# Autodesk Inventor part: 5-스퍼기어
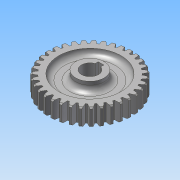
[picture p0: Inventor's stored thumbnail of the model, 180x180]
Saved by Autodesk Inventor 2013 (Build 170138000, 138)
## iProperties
Created: 2013-08
Part Number: 5-스퍼기어
Material: 강
Document SubType Name: Modeling
Designer: 한국산업디자인학원
Categories: <?xml version="1.0" encoding="UTF-16"?> <MemberInstance><Categories><FamilyTemplate><FamilyTemplateParameter ValueType="xs:double" Id="1" ObjectReferenceKey="da
Density: 1 g/cm^3
CustomPartVersion: 1
Author: 한국산업디자인학원
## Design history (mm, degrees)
sketch "Sketch1"
  geometry: C1 r 37 at (0, 0)
  constraints: 1 centre point
  dimensions: "d0" = 74 diameter of C1 (= da_da)
extrude "Extrusion1" new body sketch "Sketch1" distance "d1" = 15 (= da_b); taper "d2" = 0 deg
chamfer "모따기1" distance "d49" = 1; stored, may be unused: second distance "d50" = 2, angle "d51" = 45 deg
workplane "Work Plane2"
feature "피치 지름" dims "d4" = 10, "d5" = 0
workplane "Work Plane8"
workplane "Work Plane9"
feature "스퍼 기어" dims "da_b" = 15, "da_d" = 70, "da_aw" = 70, "da_da" = 74, "da_df" = 65, "da_dw" = 70, angle "da_beta" = 0 deg, "da_lefttooth" = 0, "da_righttooth" = 0
sketch "스케치3"
  geometry: C1 r 12.5 at (0, 0); C2 r 27.5 at (0, 0); A1 r 36 centre (0, 0) between (-30.704, -18.795) and (-29.35, -20.846) reference; A2 r 36 centre (0, 0) between (-5.215, 35.62) and (-7.633, 35.181) reference
  constraints: 2 centre point, 2 coincident
  dimensions: "d52" = 25 diameter of C1; "d54" = 55 diameter of C2
extrude "돌출2" cut sketch "스케치3" distance "d55" = 5; taper "d56" = 0 deg
sketch "스케치4"
  geometry: C1 r 12.5 at (0, 0) reference; C2 r 27.5 at (0, 0) reference
extrude "돌출3" cut sketch "스케치4" distance "d57" = 5; taper "d58" = 0 deg
sketch "스케치5"
  geometry: C1 r 12.5 at (0, 0) reference
extrude "돌출4" join sketch "스케치5" distance "d59" = 3; taper "d60" = 0 deg
node "작업 평면11"
sketch "스케치6"
  geometry: C1 r 12.5 at (0, 0) reference; 1 further point
extrude "돌출5" join sketch "스케치6" distance "d62" = 31; taper "d63" = 0 deg
sketch "스케치7"
  geometry: L1 (-2.5, 7.071)-(-2.5, 9.8); L2 (-2.5, 9.8)-(2.5, 9.8); L3 (2.5, 9.8)-(2.5, 7.071); C1 r 12.5 at (0, 0) reference; A1 r 7.5 centre (0, 0) between (-2.5, 7.071) and (2.5, 7.071); 1 further point
  constraints: 6 end point, 2 point on circle, 1 centre point, 1 coincident, 1 midpoint, 1 parallel, 1 perpendicular, 1 vertical, 1 vertical alignment
  dimensions: "d64" = 15 diameter of A1; "d66" = 5 distance of L1.end L2.end; "d67" = 17.3 dimension on A1 L2
extrude "돌출6" cut sketch "스케치7" stored distance "d68" = 31; taper "d69" = 0 deg
fillet "모깎기1" dims "d70" = 5
body "Solid1"
sketch "Sketch2"
  geometry: C1 r 37 at (0, 0) reference; C2 r 35 at (0, 0)
  constraints: 1 centre point, 1 coincident
  dimensions: "d3" = 70 diameter of C2 (= da_dw)
body "Srf1"
other parameters: "d17" = 0, "d34" = 0.8976 (computed from da_z), "d39" = 0, "d41" = 0, "d47" = 0, "d48" = 0, "d61" = 0
